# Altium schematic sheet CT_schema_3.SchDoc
size 294 x 169 mm
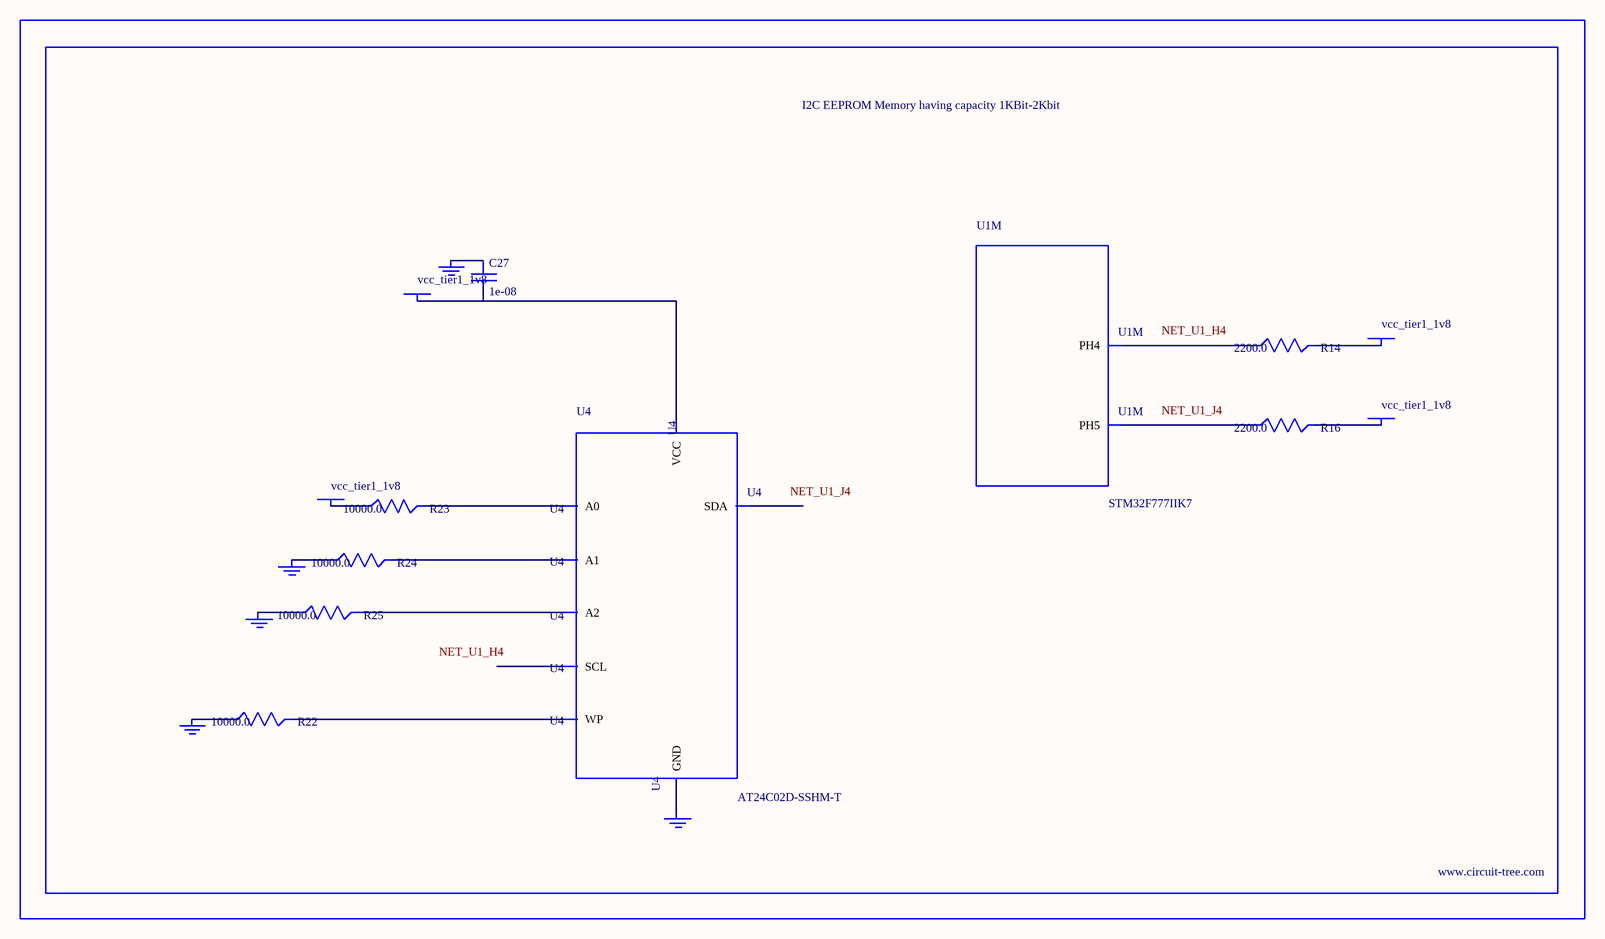
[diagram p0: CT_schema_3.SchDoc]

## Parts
BORDER2  (no value)
C27  1e-08  [C0402]
GND_INSTANCE_2_0  (no value)
GND_INSTANCE_2_1  (no value)
GND_INSTANCE_2_2  (no value)
GND_INSTANCE_2_3  (no value)
GND_INSTANCE_2_4  (no value)
POWER_INSTANCE_2_0  vcc_tier1_1v8
POWER_INSTANCE_2_1  vcc_tier1_1v8
POWER_INSTANCE_2_2  vcc_tier1_1v8
POWER_INSTANCE_2_3  vcc_tier1_1v8
R14  2200.0  [R0603]
R16  2200.0  [R0603]
R22  10000.0  [R0603]
R23  10000.0  [R0603]
R24  10000.0  [R0603]
R25  10000.0  [R0603]
U1  STM32F777IIK7  [UFBGA176_25]  (part M of 15)
U4  AT24C02D-SSHM-T  [AT24C02D]

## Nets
NetC27_1: C27.1 GND_INSTANCE_2_3.0(GND)
NetC27_2: C27.2 POWER_INSTANCE_2_1.0(PWR) U4.8(VCC)
NetGND_INSTANCE_2_0_0: GND_INSTANCE_2_0.0(GND) R24.1
NetGND_INSTANCE_2_1_0: GND_INSTANCE_2_1.0(GND) R25.1
NetGND_INSTANCE_2_2_0: GND_INSTANCE_2_2.0(GND) R22.1
NetGND_INSTANCE_2_4_0: GND_INSTANCE_2_4.0(GND) U4.4(GND)
NetPOWER_INSTANCE_2_0_0: POWER_INSTANCE_2_0.0(PWR) R23.1
NetPOWER_INSTANCE_2_2_0: POWER_INSTANCE_2_2.0(PWR) R14.2
NetPOWER_INSTANCE_2_3_0: POWER_INSTANCE_2_3.0(PWR) R16.2
NetR14_1: R14.1 U1.H4(PH4)
NetR16_1: R16.1 U1.J4(PH5)
NetR22_2: R22.2 U4.7(WP)
NetR23_2: R23.2 U4.1(A0)
NetR24_2: R24.2 U4.2(A1)
NetR25_2: R25.2 U4.3(A2)

Not connected (* = marked no-connect by the designer): U4 5(SDA) 6(SCL)

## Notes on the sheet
- Labels drawn without touching a wire or pin: NET_U1_H4, NET_U1_J4

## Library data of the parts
BORDER2 = BORDER_PAGE2
C27 = C0402C103K3RAC
GND_INSTANCE_2_0-GND_INSTANCE_2_4 = GND
POWER_INSTANCE_2_0-POWER_INSTANCE_2_3 = PWR
R14 R16 = RC0603JR-072K2L
R22-R25 = RC0603JR-0710KL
